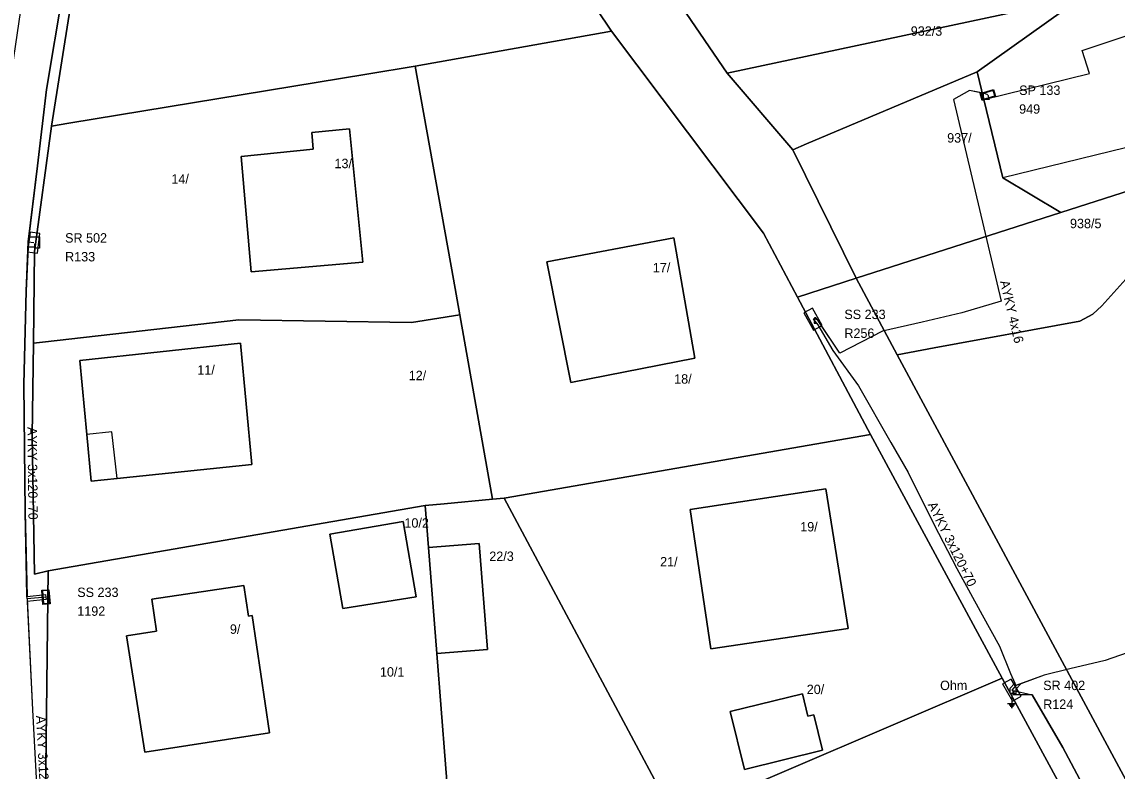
# Model space of a CAD drawing. Extents: x -793400 to -756198, y -1074141 to -1042963.
# Drawn here: x -783334.3 to -783247, y -1065199.8 to -1065140.1 of the extents above; entities that cross this region are included whole.
import ezdxf

# ---------------------------------------------------------------- set-up
doc = ezdxf.new("R2010")
doc.units = 0
for name, color, linetype in [('Parcela', 7, 'Continuous'), ('Popiskový text - Parcela', 7, 'Continuous'), ('Popiskový text - Přípojková skříň nn - SJZ', 7, 'Continuous'), ('Popiskový text - Přípojková skříň nn - Typ', 7, 'Continuous'), ('Popiskový text - Rozpojovací skříň nn - SJZ', 7, 'Continuous'), ('Popiskový text - Rozpojovací skříň nn - Typ', 7, 'Continuous'), ('Popiskový text - Uzemnění - Odpor', 7, 'Continuous'), ('Popiskový text - Vedení nn kabelové', 7, 'Continuous'), ('Skříň', 7, 'Continuous'), ('Spojnice nn', 7, 'Continuous'), ('Stavební objekt', 7, 'Continuous'), ('Uzemnění', 7, 'Continuous'), ('Vedení nn kabelové', 7, 'Continuous')]:
    doc.layers.add(name, color=color, linetype=linetype)

msp = doc.modelspace()

# ---------------------------------------------------------------- linework, layer by layer
at = {"layer": 'Parcela'}
for points in [[(-783242.83, -1065136.63), (-783249.82, -1065138.12), (-783278.06, -1065144.14), (-783307.38, -1065101.23), (-783237.38, -1065072.22)], [(-783237.43, -1065216.95), (-783264.5, -1065166.6), (-783261.55, -1065166.06), (-783249.93, -1065163.93), (-783248.89, -1065163.36), (-783248.18, -1065162.7), (-783244.84, -1065158.97)]]:
    msp.add_lwpolyline(points, dxfattribs=at)
for points in [[(-783267.78, -1065160.5), (-783272.44, -1065162), (-783275.15, -1065156.9), (-783287.28, -1065140.81), (-783310.58, -1065106.07), (-783307.38, -1065101.23), (-783278.06, -1065144.14), (-783272.83, -1065150.26)], [(-783330.54, -1065148.15), (-783331.93, -1065148.39), (-783328.95, -1065129.54), (-783325.71, -1065116.67), (-783324.47, -1065115.8), (-783310.58, -1065106.07), (-783287.28, -1065140.81), (-783302.94, -1065143.6), (-783306.79, -1065144.23)], [(-783333.46, -1065173.04), (-783333.27, -1065184.1), (-783332.18, -1065183.83), (-783332.44, -1065204.1), (-783331.2, -1065229.69), (-783329.02, -1065234.74), (-783333.33, -1065281.22), (-783340.36, -1065267.55), (-783335.58, -1065250.68), (-783334.84, -1065248.08), (-783334.44, -1065245.21), (-783335.73, -1065216.58), (-783336.76, -1065193.79), (-783337.72, -1065163.69), (-783337.71, -1065162.3), (-783336.8, -1065155.92), (-783334.89, -1065142.75), (-783332.76, -1065128.1), (-783330.21, -1065117.78), (-783325.71, -1065116.67), (-783328.95, -1065129.54), (-783331.93, -1065148.39), (-783333.28, -1065158.38), (-783333.36, -1065165.67)], [(-783238.19, -1065151), (-783251.45, -1065155.25), (-783256.08, -1065152.5), (-783257.6, -1065146.24), (-783258.13, -1065144.05), (-783249.82, -1065138.12), (-783242.83, -1065136.63), (-783239.65, -1065146.32)], [(-783271.73, -1065149.79), (-783272.83, -1065150.26), (-783278.06, -1065144.14), (-783249.82, -1065138.12), (-783258.13, -1065144.05)], [(-783295.83, -1065178.05), (-783296.77, -1065178.13), (-783299.38, -1065163.43), (-783299.88, -1065160.59), (-783302.94, -1065143.6), (-783287.28, -1065140.81), (-783275.15, -1065156.9), (-783272.44, -1065162), (-783266.62, -1065172.96)], [(-783299.38, -1065163.43), (-783303.23, -1065164.02), (-783316.99, -1065163.81), (-783332.63, -1065165.59), (-783333.36, -1065165.67), (-783333.28, -1065158.38), (-783331.93, -1065148.39), (-783330.54, -1065148.15), (-783306.79, -1065144.23), (-783302.94, -1065143.6), (-783299.88, -1065160.59)], [(-783251.45, -1065155.25), (-783267.78, -1065160.5), (-783272.83, -1065150.26), (-783271.73, -1065149.79), (-783258.13, -1065144.05), (-783257.6, -1065146.24), (-783256.08, -1065152.5)], [(-783307.09, -1065159.21), (-783308.16, -1065148.59), (-783311.18, -1065148.88), (-783311.05, -1065150.22), (-783316.81, -1065150.79), (-783316, -1065160)], [(-783307.09, -1065159.21), (-783316, -1065160), (-783316.81, -1065150.79), (-783311.05, -1065150.22), (-783311.18, -1065148.88), (-783308.16, -1065148.59)], [(-783261.55, -1065166.06), (-783264.5, -1065166.6), (-783267.78, -1065160.5), (-783251.45, -1065155.25), (-783238.19, -1065151), (-783237.26, -1065153.88), (-783238.25, -1065154.36), (-783242.96, -1065157.39), (-783244.84, -1065158.97), (-783248.18, -1065162.7), (-783248.89, -1065163.36), (-783249.93, -1065163.93)], [(-783280.63, -1065166.88), (-783290.52, -1065168.81), (-783292.43, -1065159.2), (-783282.31, -1065157.29)], [(-783280.63, -1065166.88), (-783282.31, -1065157.29), (-783292.43, -1065159.2), (-783290.52, -1065168.81)], [(-783237.43, -1065216.95), (-783199.83, -1065235.73), (-783196.65, -1065233.93), (-783194.28, -1065241.77), (-783178.12, -1065292.05), (-783173.32, -1065294.4), (-783177.68, -1065296.84), (-783187.72, -1065300.11), (-783190.56, -1065290.52), (-783205.72, -1065239.34), (-783207.03, -1065237.99), (-783208.59, -1065236.96), (-783235.05, -1065225.06), (-783238.13, -1065225.57), (-783243.03, -1065216.54), (-783256.12, -1065192.4), (-783266.62, -1065172.96), (-783272.44, -1065162), (-783267.78, -1065160.5), (-783264.5, -1065166.6)], [(-783299.38, -1065163.43), (-783296.77, -1065178.13), (-783300.61, -1065178.48), (-783302.13, -1065178.62), (-783332.18, -1065183.83), (-783333.27, -1065184.1), (-783333.46, -1065173.04), (-783333.36, -1065165.67), (-783332.63, -1065165.59), (-783316.99, -1065163.81), (-783303.23, -1065164.02)], [(-783326.7, -1065176.47), (-783328.75, -1065176.68), (-783329.1, -1065172.95), (-783329.66, -1065167.05), (-783316.85, -1065165.69), (-783315.95, -1065175.35)], [(-783326.7, -1065176.47), (-783315.95, -1065175.35), (-783316.85, -1065165.69), (-783329.66, -1065167.05), (-783329.1, -1065172.95), (-783328.75, -1065176.68)], [(-783256.12, -1065192.4), (-783282.21, -1065203.56), (-783295.83, -1065178.05), (-783266.62, -1065172.96)], [(-783268.42, -1065188.43), (-783279.35, -1065190.06), (-783281, -1065178.95), (-783270.18, -1065177.29)], [(-783268.42, -1065188.43), (-783270.18, -1065177.29), (-783281, -1065178.95), (-783279.35, -1065190.06)], [(-783295.83, -1065178.05), (-783282.21, -1065203.56), (-783272.91, -1065221.1), (-783298.39, -1065224.9), (-783300.17, -1065203.66), (-783301.21, -1065190.43), (-783297.17, -1065190.11), (-783297.83, -1065181.66), (-783301.87, -1065181.98), (-783302.13, -1065178.62), (-783300.61, -1065178.48), (-783296.77, -1065178.13)], [(-783300.17, -1065203.66), (-783332.44, -1065204.1), (-783332.18, -1065183.83), (-783302.13, -1065178.62), (-783301.87, -1065181.98), (-783301.21, -1065190.43)], [(-783302.85, -1065185.91), (-783308.7, -1065186.83), (-783309.73, -1065180.91), (-783303.89, -1065179.91)], [(-783302.85, -1065185.91), (-783303.89, -1065179.91), (-783309.73, -1065180.91), (-783308.7, -1065186.83)], [(-783297.17, -1065190.11), (-783301.21, -1065190.43), (-783301.87, -1065181.98), (-783297.83, -1065181.66)], [(-783316.58, -1065184.99), (-783316.22, -1065187.44), (-783315.92, -1065187.4), (-783314.55, -1065196.75), (-783324.49, -1065198.29), (-783325.94, -1065189.01), (-783323.56, -1065188.63), (-783323.93, -1065186.08)], [(-783316.58, -1065184.99), (-783323.93, -1065186.08), (-783323.56, -1065188.63), (-783325.94, -1065189.01), (-783324.49, -1065198.29), (-783314.55, -1065196.75), (-783315.92, -1065187.4), (-783316.22, -1065187.44)], [(-783243.03, -1065216.54), (-783272.91, -1065221.1), (-783282.21, -1065203.56), (-783256.12, -1065192.4)], [(-783272.06, -1065193.64), (-783277.82, -1065195.05), (-783276.68, -1065199.66), (-783270.46, -1065198.14), (-783271.14, -1065195.32), (-783271.62, -1065195.43)], [(-783272.06, -1065193.64), (-783271.62, -1065195.43), (-783271.14, -1065195.32), (-783270.46, -1065198.14), (-783276.68, -1065199.66), (-783277.82, -1065195.05)]]:
    msp.add_lwpolyline(points, close=True, dxfattribs=at)
at = {"layer": 'Skříň'}
for points in [[(-783256.658, -1065145.988), (-783257.733, -1065146.319), (-783257.898, -1065145.781), (-783256.823, -1065145.451)], [(-783257.696, -1065146.249), (-783256.728, -1065145.951), (-783256.86, -1065145.521), (-783257.828, -1065145.819)], [(-783333.629, -1065156.828), (-783333.832, -1065158.39), (-783333.051, -1065158.492), (-783332.848, -1065156.93)], [(-783271.933, -1065163.252), (-783271.184, -1065164.638), (-783270.491, -1065164.264), (-783271.24, -1065162.878)], [(-783332.139, -1065185.335), (-783332.041, -1065186.456), (-783332.601, -1065186.505), (-783332.7, -1065185.384)], [(-783332.102, -1065186.405), (-783332.19, -1065185.396), (-783332.639, -1065185.435), (-783332.55, -1065186.444)], [(-783254.625, -1065193.825), (-783255.413, -1065192.461), (-783256.095, -1065192.855), (-783255.307, -1065194.219)]]:
    msp.add_lwpolyline(points, close=True, dxfattribs=at)
at = {"layer": 'Spojnice nn'}
for p, q in [((-783333.77, -1065157.61), (-783333.34, -1065157.66)), ((-783332.37, -1065185.92), (-783333.868, -1065186.072)), ((-783255.04, -1065192.98), (-783255.36, -1065193.34)), ((-783255.36, -1065193.34), (-783253.75, -1065193.72))]:
    msp.add_line(p, q, dxfattribs=at)
for points in [[(-783333.77, -1065157.61), (-783333.04, -1065151.53), (-783332.31, -1065145.45), (-783331.03, -1065137.655), (-783329.75, -1065129.86), (-783327.93, -1065123.345), (-783326.11, -1065116.83), (-783323.56, -1065113.71), (-783322.97, -1065113.35)], [(-783257.278, -1065145.885), (-783257.47, -1065145.79), (-783258.74, -1065145.54), (-783260, -1065146.26), (-783256.2, -1065162.33), (-783259.36, -1065163.27), (-783262.51, -1065164), (-783265.66, -1065164.73), (-783269.06, -1065166.49), (-783270.84, -1065163.84)], [(-783333.868, -1065186.072), (-783333.88, -1065185.83), (-783334.02, -1065179.135), (-783334.125, -1065168.95), (-783333.93, -1065161.535), (-783333.77, -1065157.61)], [(-783270.84, -1065163.84), (-783271.07, -1065163.745), (-783271.212, -1065163.758)], [(-783271.212, -1065163.758), (-783270.82, -1065164.22), (-783269.62, -1065166.26), (-783267.58, -1065169.09), (-783265.01, -1065173.59), (-783263.63, -1065176), (-783261.59, -1065180.12), (-783259.75, -1065183.65), (-783257.72, -1065187.35), (-783256.34, -1065189.85), (-783255.46, -1065192.03), (-783255.04, -1065192.98)], [(-783234.75, -1065185.22), (-783234.81, -1065185.93), (-783235.25, -1065186.7), (-783237.31, -1065187.81), (-783243.04, -1065189.13), (-783244.32, -1065189.73), (-783247.91, -1065190.97), (-783250.74, -1065191.64), (-783252.77, -1065192.15), (-783255.04, -1065192.98)], [(-783333.868, -1065186.072), (-783333.425, -1065194.905), (-783333.052, -1065202.339), (-783332.97, -1065203.98), (-783332.953, -1065204.529)], [(-783253.75, -1065193.72), (-783251.3, -1065197.91), (-783248.15, -1065203.825), (-783245, -1065209.74), (-783243.39, -1065212.88), (-783241.78, -1065216.02), (-783242.02, -1065216.48), (-783243.335, -1065217.18), (-783244.65, -1065217.88), (-783251.075, -1065218.845), (-783257.5, -1065219.81), (-783262.935, -1065220.63), (-783268.37, -1065221.45), (-783273.755, -1065222.005), (-783275.07, -1065222.14)]]:
    msp.add_lwpolyline(points, dxfattribs=at)
at = {"layer": 'Stavební objekt'}
for points in [[(-783243.81, -1065149.5), (-783256.08, -1065152.5), (-783257.6, -1065146.24), (-783249.16, -1065144.18), (-783249.76, -1065142.34), (-783246.32, -1065141.2)], [(-783307.09, -1065159.21), (-783316, -1065160), (-783316.81, -1065150.79), (-783311.05, -1065150.22), (-783311.18, -1065148.88), (-783308.16, -1065148.59)], [(-783280.63, -1065166.88), (-783290.52, -1065168.81), (-783292.43, -1065159.2), (-783282.31, -1065157.29)], [(-783316.85, -1065165.69), (-783315.95, -1065175.35), (-783326.7, -1065176.47), (-783327.11, -1065172.76), (-783329.1, -1065172.95), (-783329.66, -1065167.05)], [(-783268.42, -1065188.43), (-783279.35, -1065190.06), (-783281, -1065178.95), (-783270.18, -1065177.29)], [(-783302.85, -1065185.91), (-783308.7, -1065186.83), (-783309.73, -1065180.91), (-783303.89, -1065179.91)], [(-783316.58, -1065184.99), (-783316.22, -1065187.44), (-783315.92, -1065187.4), (-783314.55, -1065196.75), (-783324.49, -1065198.29), (-783325.94, -1065189.01), (-783323.56, -1065188.63), (-783323.93, -1065186.08)], [(-783272.06, -1065193.64), (-783271.62, -1065195.43), (-783271.14, -1065195.32), (-783270.46, -1065198.14), (-783276.68, -1065199.66), (-783277.82, -1065195.05)]]:
    msp.add_lwpolyline(points, close=True, dxfattribs=at)
at = {"layer": 'Uzemnění'}
for p, q in [((-783255.36, -1065193.734), (-783255.36, -1065194.419)), ((-783255.706, -1065194.418), (-783255.015, -1065194.419)), ((-783255.581, -1065194.51), (-783255.14, -1065194.511)), ((-783255.505, -1065194.61), (-783255.22, -1065194.61)), ((-783255.412, -1065194.717), (-783255.312, -1065194.717))]:
    msp.add_line(p, q, dxfattribs=at)
at = {"layer": 'Vedení nn kabelové'}
for points in [[(-783322.655, -1065113.66), (-783322.655, -1065114.027), (-783323.2, -1065114.027), (-783323.2, -1065113.49), (-783323.56, -1065113.71), (-783326.11, -1065116.83), (-783327.93, -1065123.345), (-783329.75, -1065129.86), (-783331.03, -1065137.655), (-783332.31, -1065145.45), (-783333.04, -1065151.53), (-783333.722, -1065157.21), (-783332.879, -1065157.21), (-783332.879, -1065158.117), (-783333.245, -1065158.117), (-783333.245, -1065157.749)], [(-783257.278, -1065145.885), (-783257.178, -1065146.244), (-783257.628, -1065146.244), (-783257.628, -1065145.759), (-783258.74, -1065145.54), (-783260, -1065146.26), (-783256.2, -1065162.33), (-783259.36, -1065163.27), (-783262.51, -1065164), (-783265.66, -1065164.73), (-783269.06, -1065166.49), (-783270.639, -1065164.14), (-783270.837, -1065163.846), (-783270.983, -1065163.671), (-783271.099, -1065163.671), (-783271.099, -1065163.848)], [(-783333.22, -1065157.749), (-783333.22, -1065158.017), (-783333.69, -1065158.017), (-783333.787, -1065158.017), (-783333.93, -1065161.535), (-783334.125, -1065168.95), (-783334.02, -1065179.135), (-783333.872, -1065185.872), (-783332.39, -1065185.721), (-783332.37, -1065185.92)], [(-783271.124, -1065163.958), (-783271.124, -1065164.098), (-783270.924, -1065164.098), (-783270.82, -1065164.22), (-783269.62, -1065166.26), (-783267.58, -1065169.09), (-783265.01, -1065173.59), (-783263.63, -1065176), (-783261.59, -1065180.12), (-783259.75, -1065183.65), (-783257.72, -1065187.35), (-783256.34, -1065189.85), (-783255.46, -1065192.03), (-783255.129, -1065192.779), (-783255.51, -1065193.207), (-783255.51, -1065193.582), (-783255.177, -1065193.582), (-783255.177, -1065193.429)], [(-783238.32, -1065179.475), (-783238.32, -1065179.739), (-783238.32, -1065180.175), (-783236.117, -1065180.175), (-783236.117, -1065184.085), (-783234.917, -1065186.117), (-783235.25, -1065186.7), (-783237.31, -1065187.81), (-783243.04, -1065189.13), (-783244.32, -1065189.73), (-783247.91, -1065190.97), (-783250.74, -1065191.64), (-783252.77, -1065192.15), (-783254.644, -1065192.835), (-783255.034, -1065193.275), (-783255.034, -1065193.637), (-783255.203, -1065193.637), (-783255.203, -1065193.429)], [(-783332.37, -1065185.92), (-783332.35, -1065186.119), (-783333.858, -1065186.272), (-783333.425, -1065194.905), (-783333.052, -1065202.339), (-783332.97, -1065203.98), (-783332.959, -1065204.329), (-783331.854, -1065204.292), (-783331.854, -1065204.822), (-783331.705, -1065204.822), (-783331.705, -1065204.694), (-783331.7, -1065204.689)], [(-783275.13, -1065221.67), (-783274.932, -1065221.645), (-783274.871, -1065222.12), (-783273.755, -1065222.005), (-783268.37, -1065221.45), (-783262.935, -1065220.63), (-783257.5, -1065219.81), (-783251.075, -1065218.845), (-783244.65, -1065217.88), (-783243.335, -1065217.18), (-783242.02, -1065216.48), (-783241.78, -1065216.02), (-783243.39, -1065212.88), (-783245, -1065209.74), (-783248.15, -1065203.825), (-783251.3, -1065197.91), (-783253.75, -1065193.72), (-783255.253, -1065193.72), (-783255.253, -1065193.429)]]:
    msp.add_lwpolyline(points, dxfattribs=at)

# ---------------------------------------------------------------- texts
at = {"layer": 'Popiskový text - Parcela'}
for s, p in [('932/3', (-783263.418, -1065141.168)), ('937/', (-783260.516, -1065149.684)), ('13/', (-783309.362, -1065151.727)), ('14/', (-783322.365, -1065152.96)), ('938/5', (-783250.723, -1065156.512)), ('17/', (-783283.981, -1065160.029)), ('11/', (-783320.299, -1065168.192)), ('12/', (-783303.443, -1065168.63)), ('18/', (-783282.28, -1065168.907)), ('10/2', (-783303.786, -1065180.389)), ('19/', (-783272.232, -1065180.691)), ('22/3', (-783297.02, -1065183.045)), ('21/', (-783283.402, -1065183.482)), ('9/', (-783317.7, -1065188.854)), ('10/1', (-783305.738, -1065192.264)), ('20/', (-783271.712, -1065193.657))]:
    msp.add_text(s, height=0.75, dxfattribs=at).set_placement(p)
at = {"layer": 'Popiskový text - Přípojková skříň nn - SJZ'}
for s, p in [('949', (-783254.778, -1065147.385)), ('1192', (-783329.87, -1065187.42))]:
    msp.add_text(s, height=0.75, dxfattribs=at).set_placement(p)
at = {"layer": 'Popiskový text - Přípojková skříň nn - Typ'}
for s, p in [('SP 133', (-783254.778, -1065145.885)), ('SS 233', (-783329.87, -1065185.92))]:
    msp.add_text(s, height=0.75, dxfattribs=at).set_placement(p)
at = {"layer": 'Popiskový text - Rozpojovací skříň nn - SJZ'}
for s, p in [('R133', (-783330.84, -1065159.16)), ('R256', (-783268.712, -1065165.258)), ('R124', (-783252.86, -1065194.84))]:
    msp.add_text(s, height=0.75, dxfattribs=at).set_placement(p)
at = {"layer": 'Popiskový text - Rozpojovací skříň nn - Typ'}
for s, p in [('SR 502', (-783330.84, -1065157.66)), ('SS 233', (-783268.712, -1065163.758)), ('SR 402', (-783252.86, -1065193.34))]:
    msp.add_text(s, height=0.75, dxfattribs=at).set_placement(p)
at = {"layer": 'Popiskový text - Uzemnění - Odpor'}
msp.add_text(' Ohm', height=0.75, dxfattribs=at).set_placement((-783261.36, -1065193.34))
at = {"layer": 'Popiskový text - Vedení nn kabelové'}
for s, rotation, p in [('AYKY 4x16', 283.32763, (-783256.314, -1065160.761)), ('AYKY 3x120+70', 270.60797, (-783333.84, -1065172.368)), ('AYKY 3x120+70', 296.33377, (-783262.088, -1065178.552)), ('AYKY 3x120+70', 272.8425, (-783333.15, -1065195.39))]:
    msp.add_text(s, height=0.75, rotation=rotation, dxfattribs=at).set_placement(p)

doc.saveas('drawing.dxf')
